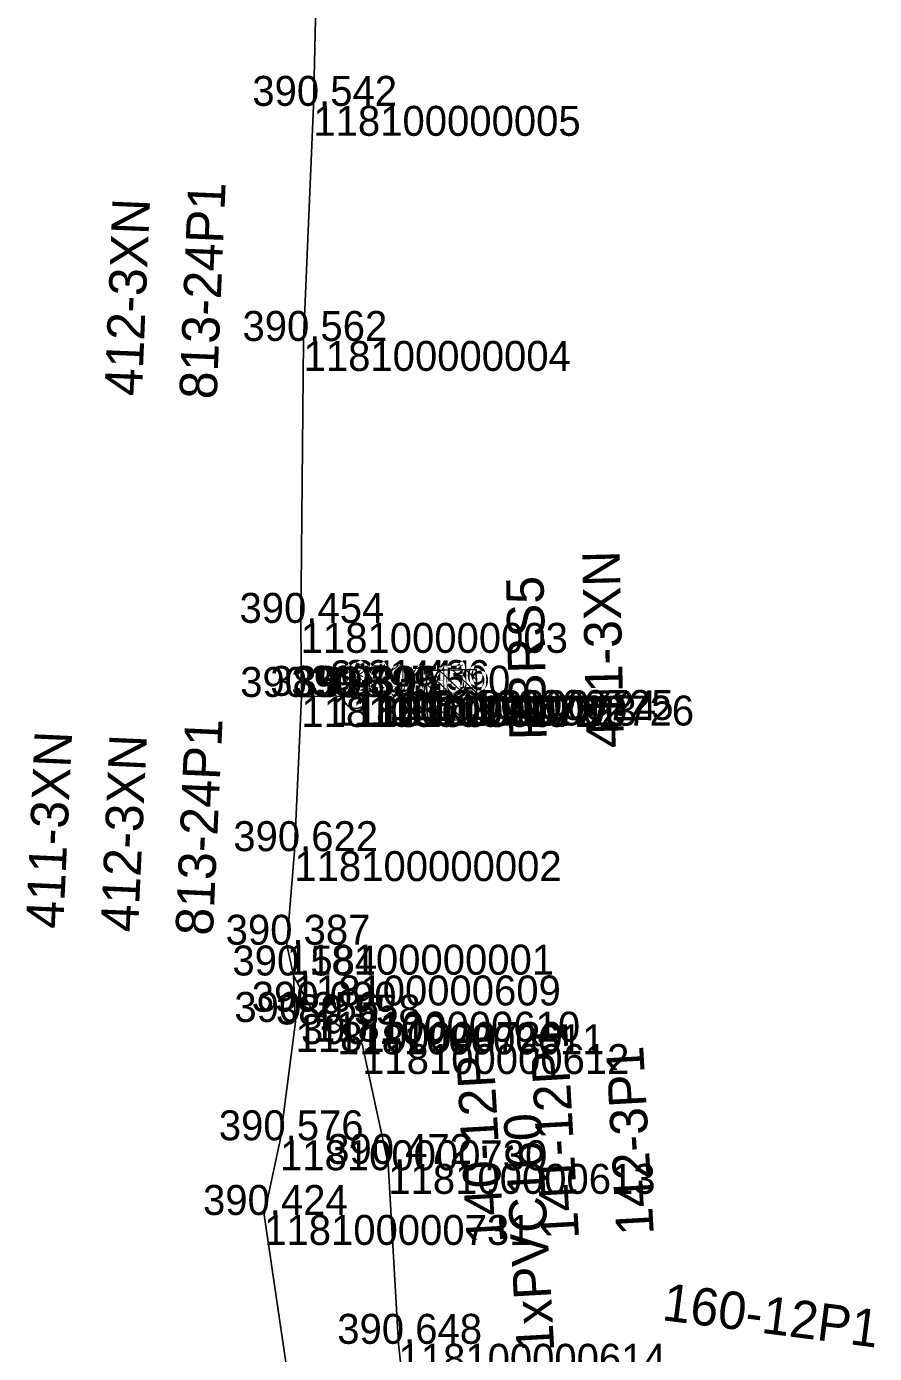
# Model space of a CAD drawing. Extents: x -724084 to -720954, y -948423 to -945131.
# Drawn here: x -721956.1 to -721922.1, y -947454 to -947400.9 of the extents above; entities that cross this region are included whole.
import ezdxf

# ---------------------------------------------------------------- set-up
doc = ezdxf.new("R2010")
doc.units = 0
for name, color, linetype in [('Vrstva 27', 7, 'Continuous'), ('Vrstva 28', 7, 'Continuous'), ('Vrstva 3', 7, 'Continuous'), ('Vrstva 31', 7, 'Continuous'), ('Vrstva 33', 7, 'Continuous'), ('Vrstva 35', 7, 'Continuous'), ('Vrstva 60', 7, 'Continuous'), ('Vrstva 61', 7, 'Continuous')]:
    doc.layers.add(name, color=color, linetype=linetype)

msp = doc.modelspace()

# ---------------------------------------------------------------- linework, layer by layer
at = {"layer": 'Vrstva 27'}
msp.add_line((-721942.872, -947427.751), (-721942.874, -947427.651), dxfattribs=at)
msp.add_lwpolyline([(-721942.873, -947427.701), (-721942.322, -947427.687), (-721941.536, -947427.473), (-721940.847, -947427.458), (-721940.024, -947427.681)], dxfattribs=at)
msp.add_circle((-721942.873, -947427.701), 0.5, dxfattribs=at)
at = {"layer": 'Vrstva 28'}
for points in [[(-721945.048, -947427.736), (-721945.079, -947424.769), (-721944.962, -947413.473), (-721944.568, -947404.055), (-721944.421, -947397.7)], [(-721945.363, -947438.895), (-721945.633, -947437.662), (-721945.33, -947433.913), (-721945.048, -947427.736)], [(-721945.048, -947427.736), (-721943.843, -947427.692), (-721942.998, -947427.741), (-721942.873, -947427.701)], [(-721945.363, -947438.895), (-721945.283, -947440.758), (-721945.907, -947445.498), (-721946.541, -947448.49), (-721945.06, -947458.57), (-721943.366, -947463.355), (-721943.216, -947468.234), (-721942.137, -947478.11), (-721942.419, -947484.356), (-721941.127, -947484.256)], [(-721942.317, -947459.17), (-721942.754, -947459.124), (-721942.67, -947458.794), (-721941.516, -947458.287), (-721940.786, -947457.115), (-721941.158, -947453.652), (-721941.567, -947446.444), (-721942.616, -947441.644), (-721943.617, -947440.857), (-721944.589, -947440.345), (-721945.363, -947438.895)]]:
    msp.add_lwpolyline(points, dxfattribs=at)
at = {"layer": 'Vrstva 3'}
for p, q in [((-721938.004, -947428.64), (-721940.045, -947426.681)), ((-721938.015, -947428.11), (-721939.515, -947426.67)), ((-721938.026, -947427.579), (-721938.984, -947426.659)), ((-721938.037, -947427.049), (-721938.454, -947426.649)), ((-721938.534, -947428.651), (-721940.034, -947427.211)), ((-721939.065, -947428.662), (-721940.023, -947427.742)), ((-721939.595, -947428.672), (-721940.012, -947428.272))]:
    msp.add_line(p, q, dxfattribs=at)
msp.add_lwpolyline([(-721940.003, -947428.681), (-721940.045, -947426.681), (-721938.045, -947426.64), (-721938.004, -947428.64)], close=True, dxfattribs=at)
at = {"layer": 'Vrstva 31'}
for points in [[(-721945.048, -947427.736), (-721945.079, -947424.769), (-721944.962, -947413.473), (-721944.568, -947404.055), (-721944.421, -947397.7)], [(-721945.363, -947438.895), (-721945.633, -947437.662), (-721945.33, -947433.913), (-721945.048, -947427.736)], [(-721945.363, -947438.895), (-721945.283, -947440.758), (-721945.907, -947445.498), (-721946.541, -947448.49), (-721945.06, -947458.57), (-721943.366, -947463.355), (-721943.216, -947468.234), (-721942.137, -947478.11), (-721942.419, -947484.356), (-721941.127, -947484.256)]]:
    msp.add_lwpolyline(points, dxfattribs=at)
at = {"layer": 'Vrstva 33'}
msp.add_lwpolyline([(-721945.06, -947458.57), (-721946.541, -947448.49), (-721945.907, -947445.498), (-721945.283, -947440.758), (-721945.363, -947438.895), (-721945.633, -947437.662), (-721945.33, -947433.913), (-721945.048, -947427.736), (-721945.079, -947424.769), (-721944.962, -947413.473), (-721944.568, -947404.055), (-721944.421, -947397.7)], dxfattribs=at)
at = {"layer": 'Vrstva 35'}
for points in [[(-721942.317, -947459.17), (-721942.754, -947459.124), (-721942.67, -947458.794), (-721941.516, -947458.287), (-721940.786, -947457.115), (-721941.158, -947453.652), (-721941.567, -947446.444), (-721942.616, -947441.644), (-721943.617, -947440.857), (-721944.589, -947440.345), (-721945.363, -947438.895)], [(-721942.419, -947484.356), (-721942.137, -947478.11), (-721943.216, -947468.234), (-721943.366, -947463.355), (-721945.06, -947458.57), (-721946.541, -947448.49)]]:
    msp.add_lwpolyline(points, dxfattribs=at)
at = {"layer": 'Vrstva 60'}
for p, q in [((-721944.568, -947404.055), (-721944.568, -947404.055)), ((-721944.962, -947413.473), (-721944.962, -947413.473)), ((-721945.079, -947424.769), (-721945.079, -947424.769)), ((-721945.048, -947427.736), (-721945.048, -947427.736)), ((-721943.843, -947427.692), (-721943.843, -947427.692)), ((-721942.998, -947427.741), (-721942.998, -947427.741)), ((-721942.873, -947427.701), (-721942.873, -947427.701)), ((-721942.322, -947427.687), (-721942.322, -947427.687)), ((-721941.536, -947427.473), (-721941.536, -947427.473)), ((-721940.847, -947427.458), (-721940.847, -947427.458)), ((-721940.024, -947427.681), (-721940.024, -947427.681)), ((-721945.33, -947433.913), (-721945.33, -947433.913)), ((-721945.633, -947437.662), (-721945.633, -947437.662)), ((-721945.363, -947438.895), (-721945.363, -947438.895)), ((-721944.589, -947440.345), (-721944.589, -947440.345)), ((-721945.283, -947440.758), (-721945.283, -947440.758)), ((-721943.617, -947440.857), (-721943.617, -947440.857)), ((-721942.616, -947441.644), (-721942.616, -947441.644)), ((-721945.907, -947445.498), (-721945.907, -947445.498)), ((-721941.567, -947446.444), (-721941.567, -947446.444)), ((-721946.541, -947448.49), (-721946.541, -947448.49)), ((-721941.158, -947453.652), (-721941.158, -947453.652))]:
    msp.add_line(p, q, dxfattribs=at)

# ---------------------------------------------------------------- texts
at = {"layer": 'Vrstva 27'}
msp.add_text('PBRS5', height=1.5, rotation=91.1765, dxfattribs=at).set_placement((-721935.214, -947429.454))
at = {"layer": 'Vrstva 28'}
for s, rotation, p in [('813-24P1', 87.6044, (-721948.448, -947415.83)), ('412-3XN', 87.6044, (-721951.445, -947415.704)), ('411-3XN', 91.3571, (-721932.114, -947429.771)), ('813-24P1', 87.3861, (-721948.603, -947437.32)), ('411-3XN', 87.3861, (-721954.597, -947437.047)), ('412-3XN', 87.3861, (-721951.6, -947437.183)), ('140-12P1', 93.2476, (-721936.917, -947449.604)), ('141-12P1', 93.2476, (-721933.921, -947449.434)), ('142-3P1', 93.2476, (-721930.926, -947449.264)), ('160-12P1', 352.6853, (-721930.637, -947452.698))]:
    msp.add_text(s, height=1.5, rotation=rotation, dxfattribs=at).set_placement(p)
at = {"layer": 'Vrstva 35'}
msp.add_text('1xPVC160', height=1.5, rotation=93.2476, dxfattribs=at).set_placement((-721934.913, -947453.946))
at = {"layer": 'Vrstva 60'}
for s, p in [('118100000005', (-721944.568, -947405.255)), ('118100000004', (-721944.962, -947414.673)), ('118100000003', (-721945.079, -947425.969)), ('118100000719', (-721945.048, -947428.936)), ('118100000720', (-721943.843, -947428.892)), ('118100000721', (-721942.998, -947428.941)), ('118100000722', (-721942.873, -947428.901)), ('118100000723', (-721942.322, -947428.887)), ('118100000724', (-721941.536, -947428.673)), ('118100000725', (-721940.847, -947428.658)), ('118100000726', (-721940.024, -947428.881)), ('118100000002', (-721945.33, -947435.113)), ('118100000001', (-721945.633, -947438.862)), ('118100000609', (-721945.363, -947440.095)), ('118100000610', (-721944.589, -947441.545)), ('118100000729', (-721945.283, -947441.958)), ('118100000611', (-721943.617, -947442.057)), ('118100000612', (-721942.616, -947442.844)), ('118100000730', (-721945.907, -947446.698)), ('118100000613', (-721941.567, -947447.644)), ('118100000731', (-721946.541, -947449.69)), ('118100000614', (-721941.158, -947454.852))]:
    msp.add_text(s, height=1.2, dxfattribs=at).set_placement(p)
at = {"layer": 'Vrstva 61'}
for s, p in [('390.542', (-721947.016, -947404.055)), ('390.562', (-721947.41, -947413.473)), ('390.454', (-721947.53, -947424.769)), ('390.598', (-721947.502, -947427.736)), ('389.983', (-721946.295, -947427.692)), ('390.399', (-721945.452, -947427.741)), ('391.305', (-721945.329, -947427.701)), ('391.171', (-721944.679, -947427.687)), ('391.441', (-721943.893, -947427.473)), ('391.436', (-721943.299, -947427.458)), ('391.590', (-721942.475, -947427.681)), ('390.622', (-721947.778, -947433.913)), ('390.387', (-721948.085, -947437.662)), ('390.584', (-721947.814, -947438.895)), ('390.090', (-721947.04, -947440.345)), ('390.256', (-721947.735, -947440.758)), ('389.558', (-721946.071, -947440.857)), ('390.100', (-721945.067, -947441.644)), ('390.576', (-721948.359, -947445.498)), ('390.472', (-721944.015, -947446.444)), ('390.424', (-721948.992, -947448.49)), ('390.648', (-721943.612, -947453.652))]:
    msp.add_text(s, height=1.2, dxfattribs=at).set_placement(p)

doc.saveas('drawing.dxf')
